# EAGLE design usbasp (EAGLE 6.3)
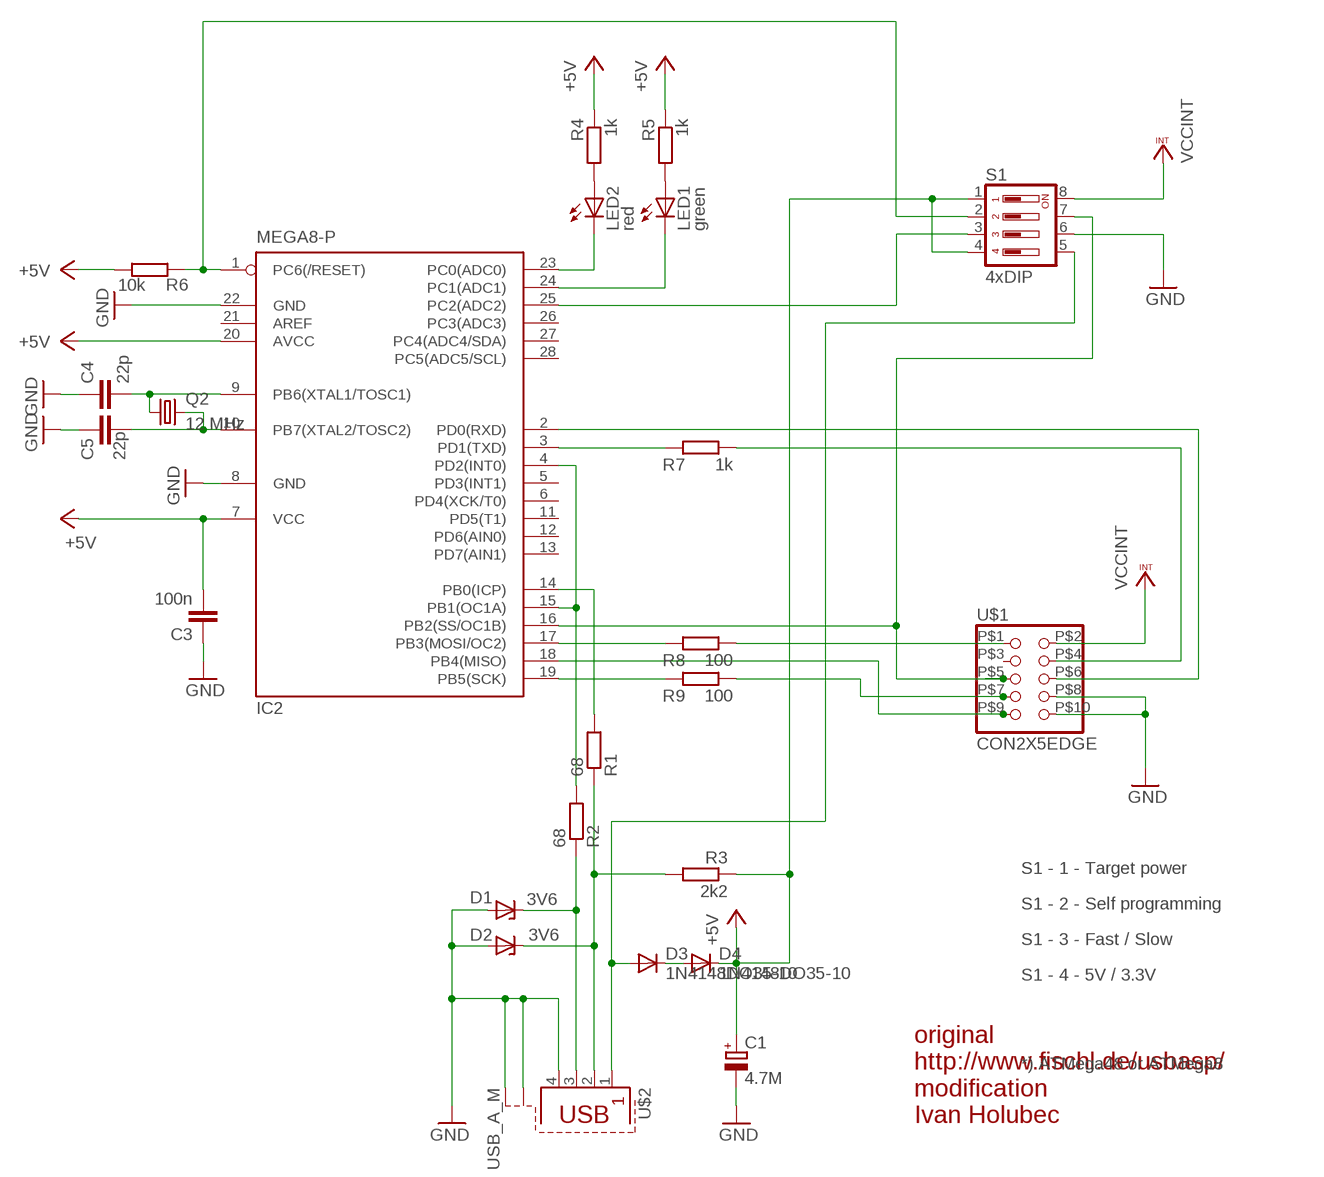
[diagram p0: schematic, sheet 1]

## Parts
C1  4.7M  CPOL-EUTT2D4L  [TT2D4L]
C3  100n  C-EU050-024X044  [C050-024X044]
C4  22p  C-EU025-024X044  [C025-024X044]
C5  22p  C-EU025-024X044  [C025-024X044]
D1  3V6  ZENER-DIODEDO34-7  [DO34Z7]
D2  3V6  ZENER-DIODEDO34-7  [DO34Z7]
D3  1N4148DO35-10  [DO35-10]
D4  1N4148DO35-10  [DO35-10]
IC2  MEGA8-P  [DIL28-3]
LED1  green  LED3MM  [LED3MM]
LED2  red  LED3MM  [LED3MM]
Q2  12 MHz  CRYSTALHC49U-V  [HC49U-V]
R1  68  R-EU_0207/10  [0207/10]
R2  68  R-EU_0207/10  [0207/10]
R3  2k2  R-EU_0207/10  [0207/10]
R4  1k  R-EU_0207/10  [0207/10]
R5  1k  R-EU_0207/10  [0207/10]
R6  10k  R-EU_0207/10  [0207/10]
R7  1k  R-EU_0207/10  [0207/10]
R8  100  R-EU_0207/10  [0207/10]
R9  100  R-EU_0207/10  [0207/10]
S1  4xDIP  DS04  [DS-04]
U$1  CON2X5EDGE  [CON2X5EDGE]
U$2  USB_A_M  [USB_M]

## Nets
+5V: C1.+ C3.2 D4.C IC2.7(VCC) IC2.20(AVCC) R3.1 R4.1 R5.1 R6.1 S1.1 S1.4
GND: C1.- C3.1 C4.1 C5.1 D1.A D2.A IC2.8(GND) IC2.22(GND) S1.6 U$1.P$8 U$1.P$10 U$2.4 U$2.S1 U$2.S2
N$1: IC2.19(PB5(SCK)) R9.2
N$2: IC2.17(PB3(MOSI/OC2)) R8.2
N$3: R8.1 U$1.P$1
N$4: R9.1 U$1.P$7
N$5: D3.C D4.A
N$6: IC2.18(PB4(MISO)) U$1.P$9
N$7: IC2.4(PD2(INT0)) IC2.15(PB1(OC1A)) R2.2
N$8: D3.A S1.5 U$2.1
N$9: IC2.3(PD1(TXD)) R7.2
N$10: R7.1 U$1.P$4
N$11: IC2.2(PD0(RXD)) U$1.P$6
N$13: LED2.A R4.2
N$14: IC2.23(PC0(ADC0)) LED2.K(C)
N$15: IC2.24(PC1(ADC1)) LED1.K(C)
N$16: IC2.14(PB0(ICP)) R1.2
N$17: D2.C R1.1 R3.2 U$2.2
N$18: D1.C R2.1 U$2.3
N$22: C4.2 IC2.9(PB6(XTAL1/TOSC1)) Q2.1
N$23: C5.2 IC2.10(PB7(XTAL2/TOSC2)) Q2.2
N$25: LED1.A R5.2
SELFPROGRAM: IC2.16(PB2(SS/OC1B)) S1.7 U$1.P$5
SELFPROGRAM2: IC2.1(PC6(/RESET)) R6.2 S1.2
SLOWSCK: IC2.25(PC2(ADC2)) S1.3
VCCINT: S1.8 U$1.P$2
Unconnected: IC2.5(PD3(INT1)) IC2.6(PD4(XCK/T0)) IC2.11(PD5(T1)) IC2.12(PD6(AIN0)) IC2.13(PD7(AIN1)) IC2.21(AREF) IC2.26(PC3(ADC3)) IC2.27(PC4(ADC4/SDA)) IC2.28(PC5(ADC5/SCL)) U$1.P$3

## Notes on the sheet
- S1 - 1 - Target power
- S1 - 2 - Self programming
- S1 - 3 - Fast / Slow
- S1 - 4 - 5V / 3.3V
- *) ATMega48 or ATMega8
- original
  http://www.fischl.de/usbasp/
  modification
  Ivan Holubec

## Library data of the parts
C1 = rcl:CPOL-EU: POLARIZED CAPACITOR, European symbol
C3-C5 = rcl:C-EU: CAPACITOR, European symbol
D1 D2 = diode:ZENER-DIODE: Z-Diode
D3 D4 = diode:1N4148: DIODE
IC2 = atmel:MEGA8-P: MICROCONTROLLER 8 Kbytes FLASH, 1 kbytes SRAM, 512 bytes EEPROM, USART, 4-channel 10 bit ADC, 2-channel 8 bit ADC Pin compatible with Atmega48, ATMega88, ATMega168 Source: avr.lbr
LED1 LED2 = led:LED: LED
Q2 = crystal:CRYSTAL: CRYSTAL
R1-R9 = rcl:R-EU_: RESISTOR, European symbol
S1 = switch-dil:DS04: DIL/CODE SWITCH; OC_FARNELL: 9471570; OC_NEWARK: unknown
U$1 = schwen:CON2X5EDGE
U$2 = schwen:USB_A_M

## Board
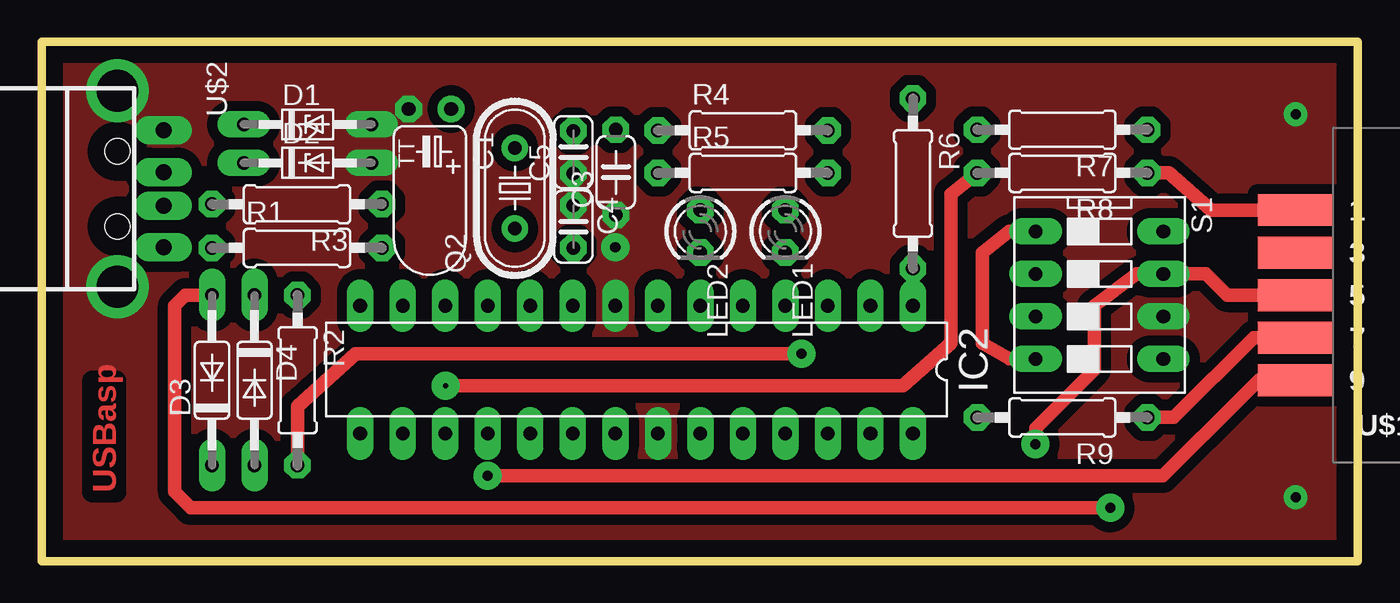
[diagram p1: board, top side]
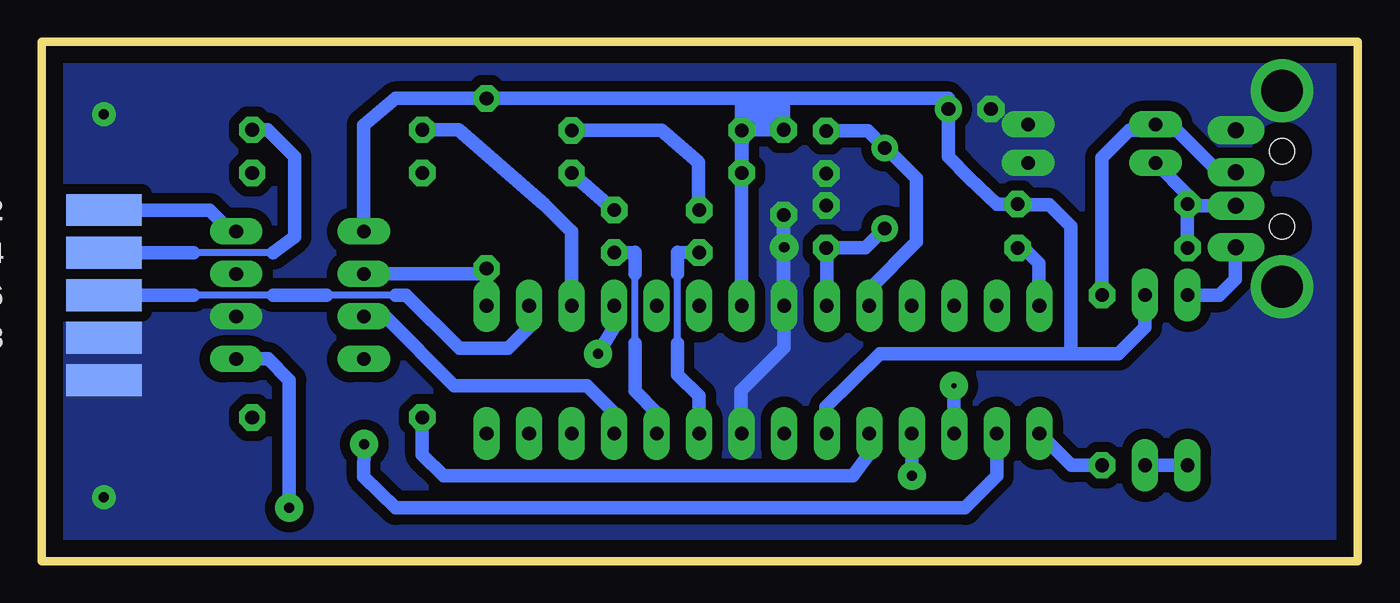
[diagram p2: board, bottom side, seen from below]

Size 78.6 x 31 mm. Coordinates in mm from the lower left corner, seen from the top.
Outline: 78.6,0 78.6,31 0,31 0,0 78.6,0
Copper layers (1*16): Top 0.035mm / dielectric 1.5mm / Bottom 0.035mm
Design rules "default *": minimum track width 10mil, minimum drill 0.3mm, track to track 8mil, track to pad 8mil, pad to pad 8mil, via to via 8mil, smd to smd 8mil, copper to edge 40mil, drill to drill 8mil, minimum pad ring 15mil, minimum via ring 15mil, stop-mask expansion 4mil, vias tented up to drill 0mil, thermal gap 10mil

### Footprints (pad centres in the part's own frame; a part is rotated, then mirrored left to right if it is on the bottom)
TT2D4L = drill 0.813 pad 1.6 round: + -1.27,0 | drill 0.813 pad 1.6 octagon: - 1.27,0
C050-024X044 = drill 0.813 octagon: 1 -2.54,0; 2 2.54,0
C025-024X044 = drill 0.813 octagon: 1 -1.27,0; 2 1.27,0
DO34Z7 = drill 0.813 long: A 3.81,0; C -3.81,0
DO35-10 = drill 0.813 long: A 5.08,0; C -5.08,0
DIL28-3 = drill 0.813 long: 1 -16.51,-3.81; 2 -13.97,-3.81; 3 -11.43,-3.81; 4 -8.89,-3.81; 5 -6.35,-3.81; 6 -3.81,-3.81; 7 -1.27,-3.81; 8 1.27,-3.81; 9 3.81,-3.81; 10 6.35,-3.81; 11 8.89,-3.81; 12 11.43,-3.81; 13 13.97,-3.81; 14 16.51,-3.81; 15 16.51,3.81; 16 13.97,3.81; 17 11.43,3.81; 18 8.89,3.81; 19 6.35,3.81; 20 3.81,3.81; 21 1.27,3.81; 22 -1.27,3.81; 23 -3.81,3.81; 24 -6.35,3.81; 25 -8.89,3.81; 26 -11.43,3.81; 27 -13.97,3.81; 28 -16.51,3.81
LED3MM = drill 0.813 octagon: A -1.27,0; K 1.27,0
HC49U-V = drill 0.813 round: 1 -2.413,0; 2 2.413,0
0207/10 = drill 0.813 octagon: 1 -5.08,0; 2 5.08,0
DS-04 = drill 0.813 long: 1 -3.81,-3.81; 2 -1.27,-3.81; 3 1.27,-3.81; 4 3.81,-3.81; 5 3.81,3.81; 6 1.27,3.81; 7 -1.27,3.81; 8 -3.81,3.81
CON2X5EDGE = smd 4.5 x 1.9: P$1 0,5.08; P$3 0,2.54; P$5 0,0; P$7 0,-2.54; P$9 0,-5.08 | smd 4.5 x 1.9 bottom: P$2 0,5.08; P$4 0,2.54; P$6 0,0; P$8 0,-2.54; P$10 0,-5.08
USB_M = drill 0.95 long: 1 3.5,0; 2 1,0; 3 -1,0; 4 -3.5,0 | drill 2.5 pad 3.5 round: S1 -5.85,-2.75; S2 5.85,-2.75 | hole 1.5: -2.25,-2.75; 2.25,-2.75

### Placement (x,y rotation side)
C1  23.18,26.99 180 top
C3  34.29,23.21 90 top
C4  31.75,19.97 270 top
C5  31.75,24.41 90 top
D1  15.88,26.07 0 top
D2  15.88,23.78 0 top
D3  10.16,10.79 90 top
D4  12.7,10.79 270 top
IC2  35.52,11.43 180 top
LED1  44.41,19.68 270 top
LED2  39.34,19.68 270 top
Q2  28.26,22.26 90 top
R1  15.24,18.7 0 top
R2  15.28,10.79 270 top
R3  15.24,21.31 180 top
R4  41.88,25.72 0 top
R5  41.88,23.18 0 top
R6  52.03,22.54 270 top
R7  60.96,25.75 180 top
R8  60.96,23.18 180 top
R9  60.96,8.57 180 top
S1  63.18,15.88 270 top
U$1  74.89,15.88 0 top
U$2  7.27,22.23 270 top
U$3  [PASSMARK]  not placed on the board
U$4  [PASSMARK]  not placed on the board

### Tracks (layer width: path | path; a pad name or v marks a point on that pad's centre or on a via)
+5V
  Top 0.813: S1.1 57.78,19.68 56.2,18.41 56.2,13.02 57.78,12.06 S1.4
  Bottom 0.254: 17.14,12.38 17.14,12.7 | 20,21.27 R3.1
  Bottom 0.813: IC2.20 31.75,7.62 31.75,9.21 28.54,12.38 17.14,12.38 14.29,12.38 12.7,13.97 D4.C | 36.8,22.54 IC2.7 | 36.8,22.54 R5.1 R4.1 36.8,27.62 | C3.2 36.76,25.75 36.8,22.54 | R3.1 21.55,21.31 23.18,22.86 24.45,24.13 C1.+ 24.45,27.62 34.29,27.62 | S1.1 59.37,26.04 57.47,27.62 R6.1 36.83,27.62 | 20.32,21.27 20,21.27 18.41,21.27 17.14,20 17.14,12.7 | 36.8,27.62 36.83,27.62 | 34.29,27.62 C3.2 | C3.2 34.29,25.72 | 34.29,27.62 36.8,27.62 | 36.83,27.62 36.2,26.67 | 36.2,26.67 36.2,26.35 34.61,26.35 34.61,26.67 36.2,26.67
GND  (via drill 0.6 pad 1.42, 0.6 pad 1.68)
  Bottom 0.406: IC2.8 34.29,15.28
  Bottom 0.813: IC2.8 34.26,12.73 36.83,10.16 36.83,7.66 IC2.22 | 34.29,15.28 C3.1
  other vias: 74.89,3.81 74.89,26.67 34.26,18.73
  pour Bottom (isolate 0.61, no thermals): -1.59,-1.91 -1.59,31.75 79.97,31.75 79.97,-1.91
  pour Top (isolate 0.61, no thermals): -0.32,-2.86 -0.32,31.75 79.97,31.75 79.97,-2.86
N$1
  Bottom 0.254: 29.21,7.58 IC2.19
  Bottom 0.813: R9.2 55.88,6.35 54.61,5.08 30.16,5.08 29.21,6.35 29.21,7.58
N$2  (via drill 0.3 pad 1.68)
  Top 0.813: v24.13,10.48 51.44,10.48 54.29,13.02 54.29,21.91 R8.2
  Bottom 0.254: 24.13,7.62 IC2.17
  Bottom 0.813: 24.13,7.58 24.13,7.62 v24.13,10.48
N$3
  Top 0.813: U$1.P$1 69.85,20.95 67.31,23.18 R8.1
N$4
  Top 0.813: U$1.P$7 72.39,13.34 67.63,8.57 R9.1
N$5
  Bottom 0.813: D3.C D4.A
N$6  (via drill 0.6 pad 1.68)
  Top 0.61: 72.71,10.79 U$1.P$9
  Top 0.813: v26.64,5.08 66.96,5.08 71.72,9.81 72.71,10.79
  Bottom 0.813: v26.64,5.08 IC2.18
N$7  (via drill 0.6 pad 1.68)
  Top 0.813: v45.37,12.38 18.73,12.38 15.28,9.24 R2.2
  Bottom 0.813: IC2.4 44.41,13.97 v45.37,12.38 | IC2.15 17.11,5.71 R2.2
N$8  (via drill 0.6 pad 1.68)
  Top 0.813: v63.82,3.17 8.89,3.17 7.94,4.13 7.94,15.24 8.57,15.88 D3.A
  Bottom 0.813: D3.A 8.26,15.88 7.3,16.83 7.3,18.37 U$2.1 | S1.5 65.09,12.06 63.82,10.79 v63.82,3.17
N$9
  Bottom 0.61: 46.95,19.68 46.99,19.68
  Bottom 0.813: 46.99,19.68 48.58,21.27 53.69,25.75 R7.2 | IC2.3 46.95,19.68
N$10
  Bottom 0.406: 64.77,18.41 69.53,18.41 | 73.03,18.41 U$1.P$4
  Bottom 0.813: R7.1 65.12,25.75 63.5,24.13 63.5,19.37 64.77,18.41 | 69.53,18.41 73.03,18.41
N$11
  Bottom 0.406: 57.47,15.88 61.59,15.88 | 64.77,15.88 69.53,15.88
  Bottom 0.61: 72.36,15.88 73.03,15.88 U$1.P$6
  Bottom 0.813: IC2.2 49.49,13.97 50.77,12.7 53.66,12.7 56.83,15.88 57.47,15.88 | 69.53,15.88 73.03,15.88 | 61.59,15.88 64.77,15.88
N$12
  Bottom 0.813: 34.61,27.3 36.2,27.3
N$13
  Bottom 0.406: LED2.A 39.37,20.99
  Bottom 0.813: R4.2 41.59,25.72 39.37,23.81 39.37,20.99
N$14
  Bottom 0.406: 40.64,13.02 40.64,17.14 | 40.64,18.41 40.64,18.45
  Bottom 0.813: IC2.23 39.34,9.88 40.64,11.11 40.64,13.02 | 40.64,18.45 LED2.K | 40.64,17.14 40.64,18.41
N$15
  Bottom 0.406: 43.18,13.02 43.18,17.14 | 43.18,18.41 43.18,18.45
  Bottom 0.813: IC2.24 41.88,8.86 43.18,10.16 43.18,13.02 | 43.18,18.45 LED1.K | 43.18,17.14 43.18,18.41
N$16
  Bottom 0.813: R1.2 19.97,18.7 19.05,17.78 19.05,15.28 IC2.14
N$17
  Bottom 0.254: R3.2 10.16,21.24
  Bottom 0.813: U$2.2 9.76,21.23 R3.2 10.16,21.87 D2.C | 10.16,21.24 R1.1
N$18
  Bottom 0.813: R2.1 15.28,24.09 13.65,25.72 12.1,25.72 D1.C 12.03,25.72 10.79,25.72 8.3,23.23 U$2.3
N$22
  Bottom 0.813: Q2.1 29.41,18.7 C4.2 31.71,18.66 IC2.9
N$23
  Bottom 0.813: IC2.10 29.18,16.23 26.35,19.05 26.35,22.86 28.26,24.77 Q2.2 29.27,25.68 C5.2
N$25
  Bottom 0.813: R5.2 46.99,23.18 LED1.A
SELFPROGRAM  (via drill 0.6 pad 1.68)
  Top 0.813: U$1.P$5 70.8,15.88 69.53,17.14 S1.7 65.41,17.14 62.87,15.24 62.87,11.43 59.37,7.94 59.37,7.02 v59.34,6.99
  Bottom 0.813: IC2.16 21.55,5.08 23.46,3.17 57.47,3.17 59.37,5.04 v59.34,6.99
SELFPROGRAM2
  Bottom 0.813: IC2.1 52.03,17.14 | 52.03,17.14 R6.2 | 52.03,17.14 S1.2
SLOWSCK
  Bottom 0.254: IC2.25 44.45,7.66
  Bottom 0.813: S1.3 58.1,14.61 53.98,10.48 46.04,10.48 44.45,8.89 44.45,7.66
VCCINT
  Bottom 0.813: U$1.P$2 68.58,20.95 67.31,19.68 S1.8

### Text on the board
Top: USBasp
